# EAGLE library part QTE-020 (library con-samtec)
THROUGH-HOLE .025" SQ POST SOCKET Source: Samtec SSW.pdf
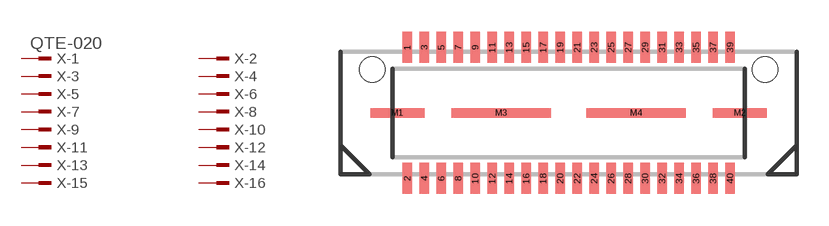
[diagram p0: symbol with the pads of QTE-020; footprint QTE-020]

Designator prefix X; gates -1=MPINV -2=MPIN -3=MPIN -4=MPIN -5=MPIN -6=MPIN -7=MPIN -8=MPIN -9=MPIN -10=MPIN -11=MPIN -12=MPIN -13=MPIN -14=MPIN -15=MPIN -16=MPIN -17=MPIN -18=MPIN -19=MPIN -20=MPIN -21=MPIN -22=MPIN -23=MPIN -24=MPIN -25=MPIN -26=MPIN -27=MPIN -28=MPIN -29=MPIN -30=MPIN -31=MPIN -32=MPIN -33=MPIN -34=MPIN -35=MPIN -36=MPIN -37=MPIN -38=MPIN -39=MPIN -40=MPIN

## QTE-020 (OC_FARNELL: unknown; OC_NEWARK: unknown)  [QTE-020]
1  -1:1  pas
2  -2:1  pas
3  -3:1  pas
4  -4:1  pas
5  -5:1  pas
6  -6:1  pas
7  -7:1  pas
8  -8:1  pas
9  -9:1  pas
10  -10:1  pas
11  -11:1  pas
12  -12:1  pas
13  -13:1  pas
14  -14:1  pas
15  -15:1  pas
16  -16:1  pas
17  -17:1  pas
18  -18:1  pas
19  -19:1  pas
20  -20:1  pas
21  -21:1  pas
22  -22:1  pas
23  -23:1  pas
24  -24:1  pas
25  -25:1  pas
26  -26:1  pas
27  -27:1  pas
28  -28:1  pas
29  -29:1  pas
30  -30:1  pas
31  -31:1  pas
32  -32:1  pas
33  -33:1  pas
34  -34:1  pas
35  -35:1  pas
36  -36:1  pas
37  -37:1  pas
38  -38:1  pas
39  -39:1  pas
40  -40:1  pas

## Footprint QTE-020 (pad centres in mm)
0,8mm HI-SPEED HEADER QTE Series Source: http://www.samtec.com/ftppub/pdf/QTE.PDF http://www.samtec.com/ftppub/cpdf/QTE-XXX-XX-X-D-XXX-FOOTPRINT.pdf
smd 0.46 x 1.45: 1 -7.595,3.09; 2 -7.595,-3.08; 3 -6.795,3.09; 4 -6.795,-3.08; 5 -5.995,3.09; 6 -5.995,-3.08; 7 -5.195,3.09; 8 -5.195,-3.08; 9 -4.395,3.09; 10 -4.395,-3.08; 11 -3.595,3.09; 12 -3.595,-3.08; 13 -2.795,3.09; 14 -2.795,-3.08; 15 -1.995,3.09; 16 -1.995,-3.08; 17 -1.195,3.09; 18 -1.195,-3.08; 19 -0.395,3.09; 20 -0.395,-3.08; 21 0.405,3.09; 22 0.405,-3.08; 23 1.205,3.09; 24 1.205,-3.08; 25 2.005,3.09; 26 2.005,-3.08; 27 2.805,3.09; 28 2.805,-3.08; 29 3.605,3.09; 30 3.605,-3.08; 31 4.405,3.09; 32 4.405,-3.08; 33 5.205,3.09; 34 5.205,-3.08; 35 6.005,3.09; 36 6.005,-3.08; 37 6.805,3.09; 38 6.805,-3.08; 39 7.605,3.09; 40 7.605,-3.08
smd 2.54 x 0.43: M1 -8.065,0; M2 8.065,0
smd 4.7 x 0.43: M3 -3.175,0; M4 3.175,0
hole 1.19 at -9.24,2.04
hole 1.19 at 9.24,2.04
